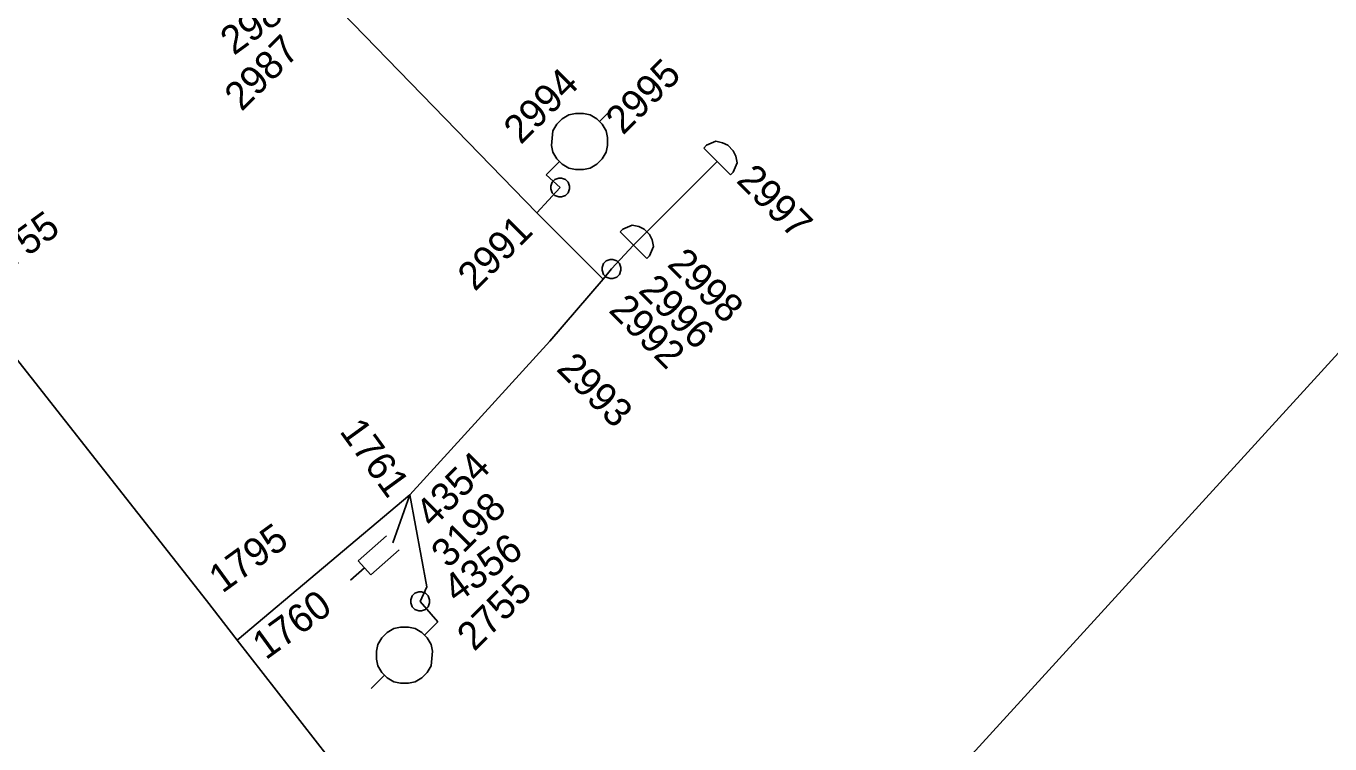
# Model space of a CAD drawing. Extents: x -535557 to -534097, y -1142175 to -1136716.
# Drawn here: x -534941.76 to -534907.24, y -1138949.07 to -1138930.06 of the extents above; entities that cross this region are included whole.
import ezdxf

# ---------------------------------------------------------------- set-up
doc = ezdxf.new("R2010")
doc.units = 0
doc.layers.add('Default', color=7, linetype='Continuous')
doc.layers.add('SS_SZDC', color=7, linetype='Continuous')

# ---------------------------------------------------------------- blocks, each defined once
blk = doc.blocks.new('POINT_DISPLAY')
at = {"layer": 'Default'}
blk.add_line((0, 0), (0, 0), dxfattribs=at)

msp = doc.modelspace()

# ---------------------------------------------------------------- linework, layer by layer
at = {"layer": 'SS_SZDC'}
for p, q in [((-534926.84, -1138960.43), (-534892.319, -1138922.61)), ((-534928.239, -1138935), (-534933.71, -1138929.37)), ((-534927.707, -1138932.656), (-534927.565, -1138932.515)), ((-534927.565, -1138932.515), (-534927.388, -1138932.409)), ((-534927.388, -1138932.409), (-534927.212, -1138932.373)), ((-534927.212, -1138932.373), (-534927, -1138932.373)), ((-534927, -1138932.373), (-534926.823, -1138932.409)), ((-534926.823, -1138932.409), (-534926.646, -1138932.515)), ((-534926.646, -1138932.515), (-534926.505, -1138932.656)), ((-534926.575, -1138932.585), (-534926.222, -1138932.232)), ((-534927.848, -1138933.222), (-534927.813, -1138932.833)), ((-534927.813, -1138932.833), (-534927.707, -1138932.656)), ((-534926.505, -1138932.656), (-534926.399, -1138932.833)), ((-534926.399, -1138932.833), (-534926.363, -1138933.01)), ((-534927.813, -1138933.398), (-534927.848, -1138933.222)), ((-534926.363, -1138933.222), (-534926.399, -1138933.398)), ((-534926.363, -1138933.01), (-534926.363, -1138933.222)), ((-534923.742, -1138933.215), (-534923.813, -1138933.286)), ((-534923.495, -1138933.109), (-534923.742, -1138933.215)), ((-534923.318, -1138933.145), (-534923.495, -1138933.109)), ((-534923.177, -1138933.215), (-534923.318, -1138933.145)), ((-534923.035, -1138933.357), (-534923.177, -1138933.215)), ((-534927.707, -1138933.575), (-534927.813, -1138933.398)), ((-534926.399, -1138933.398), (-534926.505, -1138933.575)), ((-534923.813, -1138933.286), (-534923.106, -1138933.993)), ((-534922.965, -1138933.498), (-534923.035, -1138933.357)), ((-534922.929, -1138933.675), (-534922.965, -1138933.498)), ((-534927.989, -1138934), (-534927.636, -1138933.646)), ((-534927.636, -1138933.646), (-534927.707, -1138933.575)), ((-534927.565, -1138933.717), (-534927.636, -1138933.646)), ((-534927.388, -1138933.823), (-534927.565, -1138933.717)), ((-534927.212, -1138933.858), (-534927.388, -1138933.823)), ((-534927, -1138933.858), (-534927.212, -1138933.858)), ((-534926.823, -1138933.823), (-534927, -1138933.858)), ((-534926.646, -1138933.717), (-534926.823, -1138933.823)), ((-534926.505, -1138933.575), (-534926.646, -1138933.717)), ((-534923.46, -1138933.639), (-534925.68, -1138935.86)), ((-534923.035, -1138933.922), (-534922.929, -1138933.675)), ((-534927.619, -1138934.329), (-534927.989, -1138934)), ((-534927.867, -1138934.294), (-534927.832, -1138934.188)), ((-534927.832, -1138934.188), (-534927.761, -1138934.117)), ((-534927.761, -1138934.117), (-534927.655, -1138934.082)), ((-534927.655, -1138934.082), (-534927.584, -1138934.082)), ((-534927.584, -1138934.082), (-534927.478, -1138934.117)), ((-534927.478, -1138934.117), (-534927.407, -1138934.188)), ((-534927.407, -1138934.188), (-534927.372, -1138934.294)), ((-534923.106, -1138933.993), (-534923.035, -1138933.922)), ((-534928.239, -1138935), (-534927.619, -1138934.329)), ((-534927.867, -1138934.365), (-534927.867, -1138934.294)), ((-534927.832, -1138934.471), (-534927.867, -1138934.365)), ((-534927.761, -1138934.542), (-534927.832, -1138934.471)), ((-534927.655, -1138934.577), (-534927.761, -1138934.542)), ((-534927.584, -1138934.577), (-534927.655, -1138934.577)), ((-534927.478, -1138934.542), (-534927.584, -1138934.577)), ((-534927.407, -1138934.471), (-534927.478, -1138934.542)), ((-534927.372, -1138934.365), (-534927.407, -1138934.471)), ((-534927.372, -1138934.294), (-534927.372, -1138934.365)), ((-534926.479, -1138936.76), (-534928.239, -1138935)), ((-534925.962, -1138935.435), (-534926.033, -1138935.506)), ((-534926.033, -1138935.506), (-534925.326, -1138936.213)), ((-534925.715, -1138935.329), (-534925.962, -1138935.435)), ((-534925.538, -1138935.365), (-534925.715, -1138935.329)), ((-534925.397, -1138935.435), (-534925.538, -1138935.365)), ((-534925.255, -1138935.577), (-534925.397, -1138935.435)), ((-534925.185, -1138935.718), (-534925.255, -1138935.577)), ((-534925.68, -1138935.86), (-534926.26, -1138936.489)), ((-534925.255, -1138936.142), (-534925.149, -1138935.895)), ((-534925.149, -1138935.895), (-534925.185, -1138935.718)), ((-534926.472, -1138936.348), (-534926.401, -1138936.277)), ((-534926.401, -1138936.277), (-534926.295, -1138936.242)), ((-534926.295, -1138936.242), (-534926.224, -1138936.242)), ((-534926.224, -1138936.242), (-534926.118, -1138936.277)), ((-534926.118, -1138936.277), (-534926.047, -1138936.348)), ((-534925.326, -1138936.213), (-534925.255, -1138936.142)), ((-534926.507, -1138936.454), (-534926.472, -1138936.348)), ((-534926.507, -1138936.525), (-534926.507, -1138936.454)), ((-534926.472, -1138936.631), (-534926.507, -1138936.525)), ((-534926.26, -1138936.489), (-534926.479, -1138936.76)), ((-534926.401, -1138936.702), (-534926.472, -1138936.631)), ((-534926.047, -1138936.631), (-534926.118, -1138936.702)), ((-534926.047, -1138936.348), (-534926.012, -1138936.454)), ((-534926.012, -1138936.525), (-534926.047, -1138936.631)), ((-534926.012, -1138936.454), (-534926.012, -1138936.525)), ((-534926.479, -1138936.76), (-534927.89, -1138938.399)), ((-534926.295, -1138936.737), (-534926.401, -1138936.702)), ((-534926.224, -1138936.737), (-534926.295, -1138936.737)), ((-534926.118, -1138936.702), (-534926.224, -1138936.737)), ((-534943.42, -1138937.09), (-534936.979, -1138945.27)), ((-534931.6, -1138942.469), (-534927.89, -1138938.399)), ((-534936.17, -1138946.319), (-534931.6, -1138942.469)), ((-534931.6, -1138942.469), (-534932.05, -1138943.739)), ((-534931.149, -1138944.909), (-534931.6, -1138942.469)), ((-534932.965, -1138944.213), (-534932.215, -1138943.552)), ((-534931.884, -1138943.927), (-534932.634, -1138944.588)), ((-534932.634, -1138944.588), (-534932.965, -1138944.213)), ((-534932.8, -1138944.401), (-534933.175, -1138944.731)), ((-534931.329, -1138945.29), (-534931.149, -1138944.909)), ((-534936.979, -1138945.27), (-534936.17, -1138946.319)), ((-534931.577, -1138945.254), (-534931.542, -1138945.148)), ((-534931.577, -1138945.325), (-534931.577, -1138945.254)), ((-534931.542, -1138945.148), (-534931.471, -1138945.077)), ((-534931.471, -1138945.077), (-534931.365, -1138945.042)), ((-534931.365, -1138945.042), (-534931.294, -1138945.042)), ((-534930.859, -1138945.829), (-534931.329, -1138945.29)), ((-534931.294, -1138945.042), (-534931.188, -1138945.077)), ((-534931.188, -1138945.077), (-534931.117, -1138945.148)), ((-534931.117, -1138945.148), (-534931.082, -1138945.254)), ((-534931.082, -1138945.254), (-534931.082, -1138945.325)), ((-534931.542, -1138945.431), (-534931.577, -1138945.325)), ((-534931.471, -1138945.502), (-534931.542, -1138945.431)), ((-534931.365, -1138945.537), (-534931.471, -1138945.502)), ((-534931.294, -1138945.537), (-534931.365, -1138945.537)), ((-534931.188, -1138945.502), (-534931.294, -1138945.537)), ((-534931.117, -1138945.431), (-534931.188, -1138945.502)), ((-534931.082, -1138945.325), (-534931.117, -1138945.431)), ((-534932.026, -1138946.006), (-534931.849, -1138945.971)), ((-534931.849, -1138945.971), (-534931.637, -1138945.971)), ((-534931.637, -1138945.971), (-534931.461, -1138946.006)), ((-534930.859, -1138945.829), (-534931.213, -1138946.183)), ((-534928.319, -1138956.389), (-534936.17, -1138946.319)), ((-534932.45, -1138946.431), (-534932.344, -1138946.254)), ((-534932.344, -1138946.254), (-534932.203, -1138946.112)), ((-534932.203, -1138946.112), (-534932.026, -1138946.006)), ((-534931.461, -1138946.006), (-534931.284, -1138946.112)), ((-534931.284, -1138946.112), (-534931.213, -1138946.183)), ((-534931.213, -1138946.183), (-534931.142, -1138946.254)), ((-534931.142, -1138946.254), (-534931.036, -1138946.431)), ((-534932.486, -1138946.607), (-534932.45, -1138946.431)), ((-534932.486, -1138946.819), (-534932.486, -1138946.607)), ((-534931.036, -1138946.431), (-534931.001, -1138946.607)), ((-534931.001, -1138946.607), (-534931.036, -1138946.996)), ((-534932.45, -1138946.996), (-534932.486, -1138946.819)), ((-534932.344, -1138947.173), (-534932.45, -1138946.996)), ((-534931.036, -1138946.996), (-534931.142, -1138947.173)), ((-534932.274, -1138947.244), (-534932.627, -1138947.597)), ((-534932.203, -1138947.314), (-534932.344, -1138947.173)), ((-534932.026, -1138947.42), (-534932.203, -1138947.314)), ((-534931.284, -1138947.314), (-534931.461, -1138947.42)), ((-534931.142, -1138947.173), (-534931.284, -1138947.314)), ((-534931.849, -1138947.456), (-534932.026, -1138947.42)), ((-534931.637, -1138947.456), (-534931.849, -1138947.456)), ((-534931.461, -1138947.42), (-534931.637, -1138947.456))]:
    msp.add_line(p, q, dxfattribs=at)

# ---------------------------------------------------------------- block references
for p in [(-534923.46, -1138933.639), (-534927.989, -1138934), (-534927.619, -1138934.329), (-534927.619, -1138934.329), (-534928.239, -1138935), (-534925.68, -1138935.86), (-534926.26, -1138936.489), (-534926.26, -1138936.489), (-534926.479, -1138936.76), (-534927.89, -1138938.399), (-534931.6, -1138942.469), (-534932.05, -1138943.739), (-534931.149, -1138944.909), (-534936.979, -1138945.27), (-534931.329, -1138945.29), (-534931.329, -1138945.29), (-534930.859, -1138945.829), (-534936.17, -1138946.319)]:
    msp.add_blockref('POINT_DISPLAY', p, dxfattribs=at)

# ---------------------------------------------------------------- texts
for s, rotation, p in [('2986', 36, (-534936.26, -1138930.85)), ('2987', 45, (-534936.05, -1138932.337)), ('2995', 45, (-534925.956, -1138932.965)), ('2994', 45, (-534928.658, -1138933.216)), ('2997', 315, (-534922.984, -1138934.172)), ('1755', 36, (-534942.62, -1138936.823)), ('2991', 45, (-534929.876, -1138937.105)), ('2998', 315, (-534924.81, -1138936.392)), ('2996', 315, (-534925.58, -1138937.084)), ('2992', 315, (-534926.361, -1138937.608)), ('2993', 315, (-534927.744, -1138939.159)), ('1761', 306, (-534933.48, -1138940.79)), ('4354', 45, (-534930.997, -1138943.37)), ('3198', 45, (-534930.578, -1138944.439)), ('1795', 36, (-534936.566, -1138945.093)), ('4356', 36, (-534930.361, -1138945.361)), ('2755', 45, (-534929.895, -1138946.637)), ('1760', 36, (-534935.413, -1138946.858))]:
    msp.add_text(s, height=0.75, rotation=rotation, dxfattribs=at).set_placement(p)

doc.saveas('drawing.dxf')
